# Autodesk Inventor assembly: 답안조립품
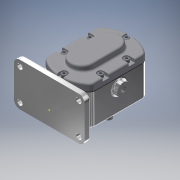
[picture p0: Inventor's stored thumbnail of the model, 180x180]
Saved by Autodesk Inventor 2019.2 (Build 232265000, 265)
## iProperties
Created: 2019-03
Part Number: 답안조립품
Material: 일반
Document SubType Name: Assembly
Designer: User
Author: User
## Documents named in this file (11)
- C:\Users\User\Desktop\490307V1026\답안조립품.iam
- C:\Users\User\Desktop\490307V1026\본체.ipt
- C:\Users\User\Desktop\490307V1026\메인축.ipt
- C:\Users\User\Desktop\490307V1026\키 6 x 6 x 18.ipt
- C:\Users\User\Desktop\490307V1026\베어링부시.ipt
- C:\Users\User\Desktop\490307V1026\서브축.ipt
- C:\Users\User\Desktop\490307V1026\스퍼기어.ipt
- C:\Users\User\Desktop\490307V1026\커버.ipt
- C:\Users\User\Desktop\490307V1026\개스킷.ipt
- C:\Users\User\Desktop\490307V1026\볼트 M5.ipt
- C:\Users\User\Desktop\490307V1026\오일 실 16 28 7.ipt
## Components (1 placed, 1 different names)
1. 개스킷:1
